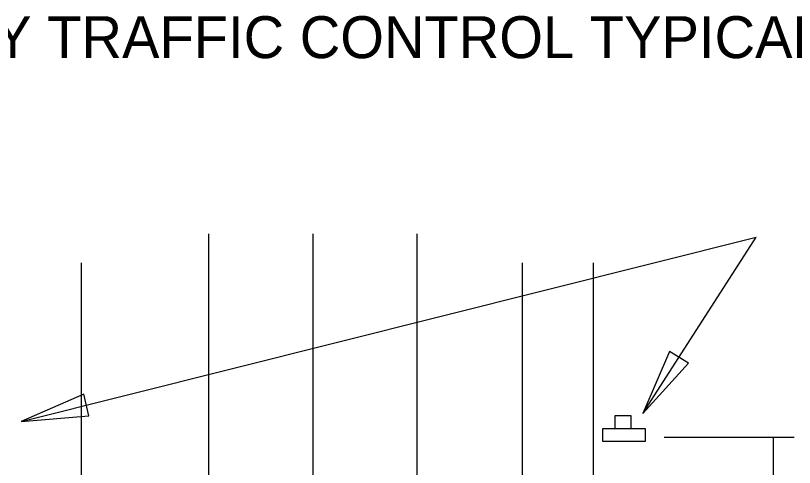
# Model space of a CAD drawing. Extents: x 15310.1 to 15319.5, y 15309 to 15319.1.
# Drawn here: x 15314.628 to 15316.632, y 15317.907 to 15319.071 of the extents above; entities that cross this region are included whole.
import ezdxf

# ---------------------------------------------------------------- set-up
doc = ezdxf.new("R2010")
doc.units = 0
for name, color, linetype in [('DETL-DIMS', 7, 'Continuous'), ('DETL-LINE', 7, 'Continuous'), ('DETL-TITL', 7, 'Continuous'), ('USER-BORD', 7, 'Continuous')]:
    doc.layers.add(name, color=color, linetype=linetype)

# ---------------------------------------------------------------- blocks, each defined once
blk = doc.blocks.new('SIGN15')
at = {"layer": 'USER-BORD'}
for points in [[(-0.013, 0.018), (0.011, 0.019), (0.011, 0.037), (-0.013, 0.037)], [(-0.031, 0.018), (-0.031, 0), (0.032, 0), (0.032, 0.018)]]:
    blk.add_lwpolyline(points, close=True, dxfattribs=at)

msp = doc.modelspace()

# ---------------------------------------------------------------- linework, layer by layer
at = {"layer": 'DETL-DIMS'}
for p, q in [((15314.643, 15318.026), (15316.534, 15318.5)), ((15316.242, 15318.046), (15316.534, 15318.5)), ((15316.297, 15317.985), (15316.632, 15317.985)), ((15316.578, 15317.985), (15316.578, 15317.426))]:
    msp.add_line(p, q, dxfattribs=at)
for points in [[(15316.36, 15318.176), (15316.311, 15318.206), (15316.242, 15318.046)], [(15314.817, 15318.04), (15314.804, 15318.096), (15314.643, 15318.026)]]:
    msp.add_lwpolyline(points, close=True, dxfattribs=at)
at = {"layer": 'DETL-LINE'}
for p, q in [((15315.126, 15310.865), (15315.126, 15318.5087)), ((15315.394, 15310.865), (15315.394, 15318.5087)), ((15315.662, 15310.865), (15315.662, 15318.5087)), ((15314.797, 15318.4337), (15314.797, 15310.79)), ((15315.932, 15318.4337), (15315.932, 15310.79)), ((15316.115, 15318.4337), (15316.115, 15310.79))]:
    msp.add_line(p, q, dxfattribs=at)
for points in [[(15315.126, 15318.065), (15315.126, 15318.14)], [(15315.394, 15318.065), (15315.394, 15318.14)], [(15315.662, 15318.065), (15315.662, 15318.14)], [(15315.126, 15317.99), (15315.126, 15318.065)], [(15315.394, 15317.99), (15315.394, 15318.065)], [(15315.662, 15317.99), (15315.662, 15318.065)]]:
    msp.add_lwpolyline(points, dxfattribs=at)

# ---------------------------------------------------------------- block references
at = {"layer": 'DETL-LINE', "xscale": 1.7523809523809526, "yscale": 1.7523809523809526}
msp.add_blockref('SIGN15', (15316.193, 15317.975), dxfattribs=at)

# ---------------------------------------------------------------- texts
at = {"layer": 'DETL-TITL'}
msp.add_text('TEMPORARY TRAFFIC CONTROL TYPICAL APPLICATION ', height=0.108, dxfattribs=at).set_placement((15313.755, 15318.961))

doc.saveas('drawing.dxf')
